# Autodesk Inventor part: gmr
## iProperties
Shininess: 77.0
Length Units: 11269
Angle Units: 11279
Time Units: 11290
Mass Units: 11283
Length Display Precision: 3
Angle Display Precision: 2
Created: 2001-12
Part Number: gmr
Document SubType Name: Modeling
Designer: Renu Muthoo
Density: 1 g/cm^3
Density: 0.0
Volumn: 0.0
Area: 0.0
PropertySet Name: Model Information
Control State: 0
Master: False
Checked Out: False
Author: Renu Muthoo
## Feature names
1. Extrusion1
2. Extrusion2
3. Extrusion3
4. Extrusion4
5. Extrusion5
6. Mirror2
7. Hole4
